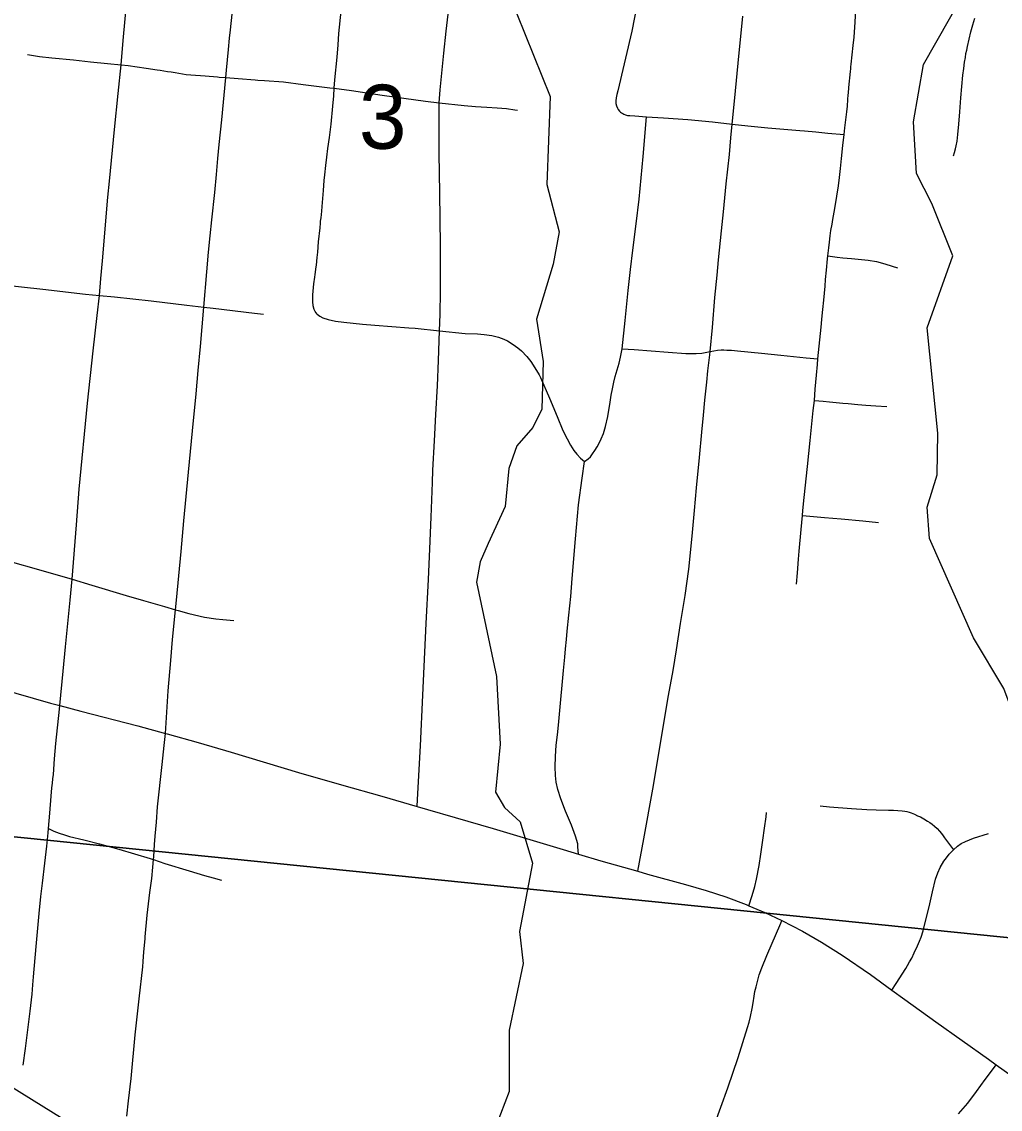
# Model space of a CAD drawing. Extents: x 0 to 34, y 0 to 22.
# Drawn here: x 5.11 to 5.749, y 18.131 to 18.842 of the extents above; entities that cross this region are included whole.
import ezdxf

# ---------------------------------------------------------------- set-up
doc = ezdxf.new("R2010")
doc.units = 0
for name, color, linetype in [('GM_X_City_Street', 7, 'Continuous'), ('GM_X_Corporation', 7, 'Continuous'), ('GM_X_County_Road', 7, 'Continuous'), ('GM_X_Minor_River', 7, 'Continuous'), ('GM_X_Rail_Line', 7, 'Continuous'), ('GM_X_Section_Text', 7, 'Continuous')]:
    doc.layers.add(name, color=color, linetype=linetype)

msp = doc.modelspace()

# ---------------------------------------------------------------- linework, layer by layer
at = {"layer": 'GM_X_City_Street'}
for points in [[(5.52548, 18.93101), (5.52353, 18.91957), (5.52108, 18.90621), (5.51311, 18.86097), (5.51161, 18.85233), (5.50817, 18.83542), (5.49907, 18.79643), (5.4985, 18.79418), (5.49805, 18.79194), (5.49781, 18.78989), (5.49789, 18.78816), (5.4982, 18.78665), (5.49884, 18.78524), (5.49945, 18.78426), (5.50022, 18.78331), (5.50094, 18.78259)], [(5.13452, 18.39457), (5.13665, 18.41705), (5.13818, 18.43293), (5.14114, 18.46346), (5.14247, 18.47721), (5.14531, 18.51271), (5.14719, 18.53615), (5.15264, 18.59233), (5.15635, 18.62641), (5.15888, 18.64966), (5.16038, 18.66273), (5.16136, 18.6737), (5.16237, 18.68545), (5.16581, 18.72691), (5.16682, 18.73741), (5.17022, 18.77114), (5.1726, 18.79478), (5.17448, 18.81344), (5.17594, 18.82945), (5.18005, 18.87452)], [(5.36805, 18.32856), (5.36828, 18.33305), (5.3701, 18.36822), (5.37167, 18.40142), (5.37382, 18.44818), (5.37532, 18.47693), (5.37625, 18.49696), (5.37722, 18.51784), (5.37811, 18.54034), (5.37832, 18.54848), (5.37938, 18.56767), (5.38022, 18.58488), (5.38126, 18.60369), (5.38199, 18.6202), (5.38259, 18.63961), (5.38293, 18.65055), (5.38315, 18.6652), (5.38331, 18.67321), (5.38323, 18.68369), (5.38326, 18.69532), (5.38286, 18.72989), (5.38239, 18.75551), (5.38239, 18.76929), (5.38239, 18.78085), (5.38239, 18.78875), (5.38295, 18.79712), (5.38536, 18.82123), (5.38698, 18.83551), (5.38994, 18.86167)], [(5.20343, 18.37636), (5.20523, 18.40424), (5.20706, 18.42404), (5.20814, 18.43767), (5.21008, 18.45715), (5.21079, 18.46352), (5.21374, 18.49525), (5.21561, 18.51531), (5.21856, 18.54712), (5.22108, 18.57419), (5.22346, 18.5983), (5.22494, 18.61376), (5.22629, 18.62924), (5.2286, 18.65507), (5.23049, 18.67813), (5.23172, 18.6911), (5.23272, 18.7016), (5.23386, 18.71209), (5.23566, 18.72997), (5.23688, 18.7417), (5.23778, 18.75221), (5.23863, 18.76147), (5.24024, 18.77761), (5.24286, 18.80521), (5.24331, 18.80996), (5.24468, 18.8235), (5.24541, 18.83087), (5.24594, 18.83639), (5.24714, 18.84663)], [(5.30255, 18.65052), (5.30138, 18.65217), (5.30064, 18.65363), (5.30007, 18.65583), (5.2998, 18.6588), (5.29986, 18.66306), (5.30056, 18.67038), (5.30121, 18.67466), (5.30136, 18.67648), (5.30204, 18.68136), (5.30218, 18.68255), (5.30267, 18.68743), (5.30299, 18.69111), (5.30355, 18.69788), (5.30449, 18.70703), (5.30473, 18.71003), (5.30485, 18.71123), (5.30517, 18.71358), (5.30558, 18.71781), (5.30582, 18.72085), (5.3067, 18.73124), (5.30727, 18.73798), (5.30759, 18.74163), (5.30835, 18.7477), (5.30898, 18.75321), (5.30968, 18.75872), (5.31066, 18.76609), (5.31176, 18.77469), (5.31297, 18.78641), (5.31343, 18.7932), (5.31379, 18.79817), (5.31419, 18.80368), (5.31566, 18.81846), (5.31631, 18.82649), (5.31683, 18.8339), (5.31827, 18.84869)], [(5.51213, 18.28618), (5.51603, 18.30732), (5.52205, 18.33991), (5.53232, 18.40106), (5.53523, 18.41755), (5.53746, 18.431), (5.54012, 18.44817), (5.54305, 18.46656), (5.54546, 18.48376), (5.54768, 18.50535), (5.54918, 18.52206), (5.55051, 18.5369), (5.5524, 18.5567), (5.55399, 18.57336), (5.55515, 18.58444), (5.55607, 18.59433), (5.55719, 18.60607), (5.55804, 18.61347), (5.55935, 18.62389), (5.55955, 18.62604), (5.56092, 18.64186), (5.5626, 18.66136), (5.56407, 18.67609), (5.56501, 18.68593), (5.56697, 18.70504), (5.5682, 18.71738), (5.56998, 18.73581), (5.57201, 18.75487), (5.57296, 18.7658), (5.57386, 18.77469), (5.57454, 18.78096), (5.57603, 18.79658), (5.57783, 18.81455), (5.58082, 18.84532)], [(5.61579, 18.47386), (5.61644, 18.48127), (5.61725, 18.49029), (5.61772, 18.49562), (5.61891, 18.50965), (5.61979, 18.51879), (5.62011, 18.52217), (5.62092, 18.53063), (5.62304, 18.55086), (5.62478, 18.56792), (5.62594, 18.57887), (5.62685, 18.58746), (5.62755, 18.59409), (5.62818, 18.60142), (5.62898, 18.61068), (5.62957, 18.61759), (5.62989, 18.62123), (5.63031, 18.62535), (5.632, 18.64199), (5.63247, 18.64689), (5.63273, 18.64933), (5.63314, 18.65361), (5.63369, 18.65967), (5.63455, 18.6689), (5.63494, 18.67317), (5.63548, 18.67926), (5.63615, 18.68663), (5.63638, 18.68866), (5.63697, 18.69395), (5.63741, 18.69759), (5.63788, 18.70173), (5.63839, 18.70522), (5.63911, 18.70939), (5.63972, 18.71247), (5.64094, 18.71948), (5.64235, 18.72772), (5.64328, 18.73434), (5.64395, 18.7399), (5.64456, 18.74567), (5.64524, 18.7523), (5.64618, 18.76078), (5.64694, 18.76803), (5.64746, 18.77242), (5.64868, 18.78285), (5.64913, 18.7865), (5.64945, 18.79076), (5.64968, 18.7938), (5.64976, 18.79501), (5.65012, 18.79867), (5.65116, 18.80908), (5.65132, 18.81091), (5.65142, 18.81213), (5.65165, 18.81392), (5.65234, 18.81995), (5.65296, 18.82607), (5.65353, 18.83159), (5.65427, 18.84148), (5.65472, 18.84952)], [(5.71852, 18.75398), (5.71921, 18.75621), (5.71982, 18.75858), (5.72027, 18.76061), (5.7208, 18.7635), (5.72134, 18.76791), (5.72202, 18.77474), (5.72259, 18.7827), (5.72336, 18.79197), (5.72467, 18.80676), (5.7252, 18.81111), (5.72575, 18.81532), (5.72622, 18.81827), (5.72662, 18.82084), (5.72711, 18.8232), (5.72761, 18.8256), (5.72866, 18.83024), (5.72989, 18.83518), (5.73114, 18.83969), (5.7325, 18.84407)], [(5.11333, 18.82025), (5.11455, 18.82003), (5.12126, 18.81897), (5.12928, 18.81817), (5.14346, 18.81672), (5.15456, 18.81556), (5.16562, 18.81431), (5.17448, 18.81344), (5.17917, 18.81298), (5.19085, 18.81144), (5.19818, 18.81034), (5.2, 18.81001), (5.20486, 18.80925), (5.2073, 18.80888), (5.20975, 18.80851), (5.21219, 18.80812), (5.21703, 18.80722), (5.22015, 18.80707), (5.22941, 18.80626), (5.23743, 18.8056), (5.23868, 18.8055), (5.24286, 18.80521), (5.25103, 18.80462), (5.2621, 18.80374), (5.26395, 18.80359), (5.26827, 18.80331), (5.28064, 18.80233), (5.29358, 18.80072), (5.31083, 18.79858), (5.31379, 18.79817), (5.32497, 18.79664), (5.3452, 18.7936), (5.3734, 18.78965), (5.38239, 18.78875), (5.39862, 18.78682), (5.40604, 18.78621), (5.41346, 18.78574), (5.42025, 18.78546), (5.42636, 18.78491), (5.43175, 18.78412), (5.43353, 18.78382)], [(5.47333, 18.2975), (5.47301, 18.30223), (5.47288, 18.30422), (5.47156, 18.30922), (5.4688, 18.31646), (5.46497, 18.3256), (5.46189, 18.33366), (5.46, 18.33961), (5.45883, 18.34449), (5.4583, 18.34884), (5.45817, 18.35448), (5.45843, 18.36135), (5.45892, 18.36857), (5.4596, 18.37548), (5.46028, 18.38171), (5.46097, 18.389), (5.4637, 18.4175), (5.46439, 18.42614), (5.46491, 18.43168), (5.46553, 18.43781), (5.46612, 18.44332), (5.4672, 18.45369), (5.46835, 18.46584), (5.46931, 18.47757), (5.47149, 18.50355), (5.47335, 18.52581), (5.47582, 18.5432), (5.47737, 18.55405), (5.47983, 18.55596), (5.4812, 18.55726), (5.48263, 18.55911), (5.4842, 18.56143), (5.48557, 18.56376), (5.48694, 18.56622), (5.48831, 18.56908), (5.48965, 18.57241), (5.49113, 18.57701), (5.49254, 18.58357), (5.49411, 18.59287), (5.49486, 18.59758), (5.49554, 18.60162), (5.49643, 18.60599), (5.49732, 18.60982), (5.49862, 18.61419), (5.49991, 18.61838), (5.50094, 18.62239), (5.50204, 18.62788), (5.50394, 18.64639), (5.50596, 18.666), (5.50736, 18.67968), (5.5089, 18.69227), (5.51103, 18.70962), (5.51301, 18.72577), (5.51578, 18.7536), (5.51775, 18.77958)], [(5.50094, 18.78259), (5.50162, 18.78203), (5.50231, 18.78161), (5.50311, 18.78116), (5.50423, 18.78073), (5.50546, 18.78048), (5.50692, 18.78033), (5.51024, 18.78008), (5.51775, 18.77958), (5.529, 18.7789), (5.54478, 18.77775), (5.56103, 18.77617), (5.57386, 18.77469), (5.58417, 18.77364), (5.59709, 18.77241), (5.60755, 18.77148), (5.61804, 18.77054), (5.62111, 18.77026), (5.62845, 18.7696), (5.63632, 18.76886), (5.64694, 18.76803)], [(5.63638, 18.68866), (5.64255, 18.68784), (5.6462, 18.68735), (5.65172, 18.68691), (5.66281, 18.68586), (5.66825, 18.68486), (5.67361, 18.68345), (5.6783, 18.68189), (5.68181, 18.68071)], [(5.0524, 18.67462), (5.05621, 18.67419), (5.07124, 18.6726), (5.09541, 18.66989), (5.12328, 18.66684), (5.15133, 18.66364), (5.16038, 18.66273), (5.17013, 18.66175), (5.19413, 18.6592), (5.21756, 18.6564), (5.2286, 18.65507), (5.23463, 18.65435), (5.26162, 18.65112), (5.26762, 18.6504)], [(5.30255, 18.65052), (5.30436, 18.6492), (5.3064, 18.64815), (5.30981, 18.64703), (5.31455, 18.64595), (5.32001, 18.64518), (5.3323, 18.64398), (5.34032, 18.64325), (5.35144, 18.64234), (5.36247, 18.64155), (5.36675, 18.64126), (5.38259, 18.63961), (5.39934, 18.63787), (5.40737, 18.63753), (5.4118, 18.63729), (5.41684, 18.63657), (5.42115, 18.63551), (5.42473, 18.63421), (5.42696, 18.63302), (5.43068, 18.63064), (5.43368, 18.62842), (5.43611, 18.62647), (5.43958, 18.62291), (5.44229, 18.61955), (5.44499, 18.61542), (5.44767, 18.61073), (5.44848, 18.60909), (5.45437, 18.5955), (5.45938, 18.58349), (5.46327, 18.57439), (5.46607, 18.5689), (5.46828, 18.56492), (5.47047, 18.5613), (5.47231, 18.5589), (5.4747, 18.55631), (5.47737, 18.55405)], [(5.50204, 18.62788), (5.50977, 18.62728), (5.52097, 18.62647), (5.5321, 18.62566), (5.54351, 18.62479), (5.54686, 18.62469), (5.55024, 18.62474), (5.55406, 18.62509), (5.55955, 18.62604), (5.56196, 18.62658), (5.56433, 18.62691), (5.56664, 18.62711), (5.56841, 18.62711), (5.57025, 18.62704), (5.57348, 18.62684), (5.57737, 18.62658), (5.59298, 18.62499), (5.6056, 18.6237), (5.62228, 18.622), (5.62989, 18.62123)], [(5.62755, 18.59409), (5.63325, 18.59355), (5.63753, 18.59315), (5.64179, 18.59273), (5.64606, 18.59233), (5.64974, 18.59201), (5.656, 18.59147), (5.66126, 18.59101), (5.66767, 18.59059), (5.67492, 18.59012)], [(5.61979, 18.51879), (5.63415, 18.51753), (5.64499, 18.51658), (5.65929, 18.51532), (5.66943, 18.51433)], [(5.0724, 18.49712), (5.11893, 18.4839), (5.14247, 18.47721), (5.15546, 18.47327), (5.17782, 18.46649), (5.18916, 18.46332), (5.20287, 18.4594), (5.21008, 18.45715), (5.2117, 18.45665), (5.21885, 18.45471), (5.22907, 18.45239), (5.23635, 18.45121), (5.2409, 18.4508), (5.24828, 18.45022)], [(5.11046, 18.15944), (5.11203, 18.17028), (5.11509, 18.19478), (5.11638, 18.20585), (5.11691, 18.21201), (5.11734, 18.2171), (5.11898, 18.23694), (5.12, 18.24903), (5.12088, 18.25857), (5.12213, 18.26983), (5.12315, 18.27835), (5.12474, 18.29162), (5.1259, 18.30268), (5.12686, 18.31129), (5.1271, 18.31415), (5.12799, 18.32422), (5.12888, 18.33524), (5.12929, 18.34076), (5.12961, 18.34375), (5.12992, 18.34676), (5.13022, 18.34958), (5.13107, 18.35969), (5.13191, 18.36972), (5.13427, 18.39212), (5.13452, 18.39457)], [(5.17828, 18.126), (5.17939, 18.13614), (5.18104, 18.15068), (5.18366, 18.17928), (5.18553, 18.19499), (5.18641, 18.20287), (5.18864, 18.22363), (5.18896, 18.2273), (5.18938, 18.23346), (5.19013, 18.2421), (5.19019, 18.24332), (5.19156, 18.25751), (5.19242, 18.26488), (5.19333, 18.27224), (5.19461, 18.28144), (5.19529, 18.28883), (5.19567, 18.29393), (5.1958, 18.29561), (5.19634, 18.30363), (5.19682, 18.30918), (5.19763, 18.31842), (5.19835, 18.32831), (5.20129, 18.35608), (5.20259, 18.36842), (5.20343, 18.37636)], [(5.58483, 18.26368), (5.58687, 18.27041), (5.58865, 18.27626), (5.58983, 18.28101), (5.5915, 18.29007), (5.59266, 18.29736), (5.59303, 18.30039), (5.59386, 18.30649), (5.595, 18.31443), (5.59599, 18.32172), (5.59636, 18.32475)], [(5.6314, 18.32892), (5.63754, 18.32846), (5.65182, 18.32728), (5.66175, 18.32652), (5.6679, 18.32641), (5.67597, 18.32627), (5.67922, 18.32621), (5.68203, 18.32606), (5.68485, 18.32579), (5.6867, 18.32552), (5.68793, 18.32526), (5.68947, 18.32483), (5.6909, 18.32436), (5.69295, 18.32345), (5.69504, 18.32257), (5.69684, 18.32172), (5.69907, 18.32055), (5.7016, 18.31904), (5.70298, 18.3181), (5.70456, 18.31692), (5.70611, 18.31563), (5.70771, 18.31412), (5.7093, 18.31245), (5.71056, 18.31098), (5.71172, 18.30945), (5.71267, 18.30812), (5.71847, 18.30027)], [(5.1271, 18.31415), (5.13047, 18.31246), (5.13398, 18.31103), (5.13743, 18.30995), (5.14082, 18.30906), (5.15016, 18.30678), (5.16046, 18.30419), (5.17313, 18.30061), (5.18336, 18.29752), (5.1936, 18.29455), (5.1948, 18.29419), (5.19567, 18.29393), (5.19931, 18.29252), (5.203, 18.29121), (5.21888, 18.28645), (5.22899, 18.28347), (5.23476, 18.28191), (5.24015, 18.28044)], [(5.6782, 18.20849), (5.68097, 18.21279), (5.68737, 18.22271), (5.68852, 18.22467), (5.68982, 18.22693), (5.69121, 18.22947), (5.69281, 18.23291), (5.69491, 18.23757), (5.69625, 18.2405), (5.69725, 18.24319), (5.69861, 18.24719), (5.69963, 18.25089), (5.70262, 18.26295), (5.70469, 18.27268), (5.70677, 18.28111), (5.70822, 18.28521), (5.70977, 18.28877), (5.71219, 18.29278), (5.71385, 18.29501), (5.71576, 18.29738), (5.71847, 18.30027), (5.72102, 18.30255), (5.72358, 18.30432), (5.72633, 18.30574), (5.73153, 18.30781), (5.74146, 18.31083)], [(5.55739, 18.1068), (5.57104, 18.14451), (5.57768, 18.1645), (5.5839, 18.18399), (5.58488, 18.1876), (5.58576, 18.19118), (5.58681, 18.19643), (5.58746, 18.20021), (5.5882, 18.20466), (5.58873, 18.20758), (5.58942, 18.21067), (5.59154, 18.21843), (5.59321, 18.22309), (5.5966, 18.23108), (5.60566, 18.25239), (5.60637, 18.25407)], [(5.72166, 18.12754), (5.72776, 18.13449), (5.73347, 18.14221), (5.73922, 18.14997), (5.7433, 18.15549), (5.74644, 18.15972)]]:
    msp.add_lwpolyline(points, dxfattribs=at)
at = {"layer": 'GM_X_Corporation'}
for points in [[(5.88653, 19.24719), (5.79402, 18.23883), (4.80587, 18.33893), (4.89829, 19.34286)], [(4.80587, 18.33893), (5.79402, 18.23883), (5.70874, 17.23111), (4.7096, 17.33101)]]:
    msp.add_lwpolyline(points, close=True, dxfattribs=at)
at = {"layer": 'GM_X_County_Road'}
for points in [[(5.02784, 18.42514), (5.02855, 18.42493), (5.06915, 18.41322), (5.0942, 18.40586), (5.1283, 18.39622), (5.13452, 18.39457)], [(5.13452, 18.39457), (5.14814, 18.39096), (5.18541, 18.38125), (5.20343, 18.37636)], [(5.20343, 18.37636), (5.20458, 18.37605), (5.22491, 18.37035), (5.24639, 18.36414), (5.29042, 18.35088), (5.31846, 18.34265), (5.34483, 18.33533), (5.36805, 18.32856)], [(5.36805, 18.32856), (5.37481, 18.32658), (5.3928, 18.32147), (5.41761, 18.31427), (5.46332, 18.30052), (5.47333, 18.2975)], [(5.47333, 18.2975), (5.48805, 18.29306), (5.51213, 18.28618)], [(5.51213, 18.28618), (5.51854, 18.28435), (5.54335, 18.27754), (5.55679, 18.27356), (5.56967, 18.2694), (5.58292, 18.26447), (5.58483, 18.26368)], [(5.58483, 18.26368), (5.59523, 18.25935), (5.60637, 18.25407)], [(5.60637, 18.25407), (5.61989, 18.24696), (5.63218, 18.23989), (5.64574, 18.23126), (5.66415, 18.21869), (5.6782, 18.20849)], [(5.6782, 18.20849), (5.68673, 18.20231), (5.70684, 18.18769), (5.74136, 18.16337), (5.74644, 18.15972)], [(5.74644, 18.15972), (5.76503, 18.14637), (5.79027, 18.12832), (5.79543, 18.12475)]]:
    msp.add_lwpolyline(points, dxfattribs=at)
at = {"layer": 'GM_X_Minor_River'}
for points in [[(5.91209, 18.12232), (5.90698, 18.15282), (5.87345, 18.20446), (5.86722, 18.21599), (5.8288, 18.27001), (5.79761, 18.32539), (5.78016, 18.34553), (5.76037, 18.38167), (5.75134, 18.40579), (5.73149, 18.4389), (5.70275, 18.50372), (5.70125, 18.52426), (5.70772, 18.54538), (5.70824, 18.57272), (5.70121, 18.64161), (5.71804, 18.68871), (5.70427, 18.72282), (5.6944, 18.74241), (5.69239, 18.77625), (5.6988, 18.81371), (5.74275, 18.89097)], [(5.43312, 18.84693), (5.45485, 18.7929), (5.45262, 18.73522), (5.46075, 18.70428), (5.45694, 18.6831), (5.44601, 18.64726), (5.45041, 18.61943), (5.44944, 18.58831), (5.44352, 18.57629), (5.43305, 18.56437), (5.42784, 18.54967), (5.42547, 18.52466), (5.41439, 18.5006), (5.40923, 18.48856), (5.4067, 18.47532), (5.41994, 18.4135), (5.42213, 18.3694), (5.41925, 18.33794), (5.42513, 18.32793), (5.4352, 18.3186), (5.44341, 18.29145), (5.43497, 18.24682), (5.43723, 18.22588), (5.42805, 18.18241), (5.42804, 18.14215), (5.41965, 18.11992)]]:
    msp.add_lwpolyline(points, dxfattribs=at)
at = {"layer": 'GM_X_Rail_Line'}
msp.add_lwpolyline([(3.83258, 18.78915), (4.04668, 18.71724), (4.20013, 18.66068), (4.27929, 18.62258), (4.42905, 18.54243), (4.65516, 18.4157), (4.85706, 18.2978), (5.4078, 17.95591), (5.67948, 17.78757), (5.87786, 17.66832)], dxfattribs=at)

# ---------------------------------------------------------------- texts
at = {"layer": 'GM_X_Section_Text'}
msp.add_text('3', height=0.04186, rotation=0.00001, dxfattribs=at).set_placement((5.32989, 18.75863))

doc.saveas('drawing.dxf')
